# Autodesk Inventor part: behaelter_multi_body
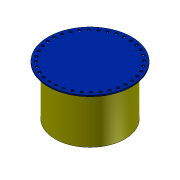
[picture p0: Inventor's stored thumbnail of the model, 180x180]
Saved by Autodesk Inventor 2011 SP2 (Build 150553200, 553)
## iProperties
Created: 2012-02
Part Number: behaelter_multi_body
Material: S235JRG2
Document SubType Name: Modeling
Designer: SCHALLA
Density: 7.85 g/cm^3
Mass: 508816 g
Surface Area: 67707.6 cm^2
Volume: 64817.3 cm^3
Author: SCHALLA
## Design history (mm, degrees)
sketch "SK_ROHR"
  geometry: C1 r 500 at (0, 0); C2 r 480 at (0, 0); 1 further point
  constraints: 2 centre point, 1 coincident
  dimensions: "d27" = 1000 diameter of C1 (= Rohr_D); "d28" = 20 radial gap between concentric circles of C1 C2 (= Rohr_T)
extrude "E_ROHR" new body sketch "SK_ROHR" stored distance "d29" = 700 (= Rohr_L); taper "d30" = 0 deg
sketch "SK_FLANSCH"
  geometry: L1 (0, 0)-(600, 0); L2 (0, 0)-(41.854, 598.538); L3 (0, 0)-(0, 550); A1 r 600 centre (0, 0) between (600, 0) and (41.854, 598.538); A2 r 550 centre (0, 0) between (38.366, 548.66) and (0, 550); 1 further point
  constraints: 6 end point, 4 point on circle, 2 centre point, 1 coincident, 1 horizontal, 1 perpendicular, 1 point on line
  dimensions: "d31" = 1200 diameter of A1 (= Flansch_D); "d35" = 1100 diameter of A2 (= Flansch_LK); "d46" = 4 deg angle of L2 L3 (= Flansch_Bohrung_Start_Winkel)
extrude "E_FLANSCH" new body sketch "SK_FLANSCH" distance "d33" = 20 (= Flansch_T); taper "d34" = 0 deg
hole "BOHRUNG_FLANSCH" sketch "SK_FLANSCH" diameter "d36" = 40 (= Flansch_Bohrung_D); stored, may be unused: countersink angle "d40" = 90 deg, drill point angle "d42" = 0 deg; dims "d37" = 6, "d38" = 4, "d39" = 2, "d41" = 20 (= Flansch_T)
node "ROHR"
pattern_circular "PATTERN_BOHRUNG_FLANSCH" dims angle "d44" = 360 deg
node "FLANSCH"
other parameters: "Rohr_D" = 1000 [user parameter; used in 2 equation terms], "Rohr_L" = 700 [user parameter; used in 1 equation term], "Rohr_T" = 20 [user parameter; used in 1 equation term], "Flansch_D" = 1200 (computed from Rohr_D) [user parameter; used in 2 equation terms], "Flansch_T" = 20 [user parameter; used in 2 equation terms], "Flansch_LK" = 1100 (computed from Flansch_D) [user parameter; used in 1 equation term], "Flansch_Bohrung_Start_Winkel" = 4 deg [user parameter; used in 1 equation term], "Flansch_Bohrung_D" = 40 [user parameter; used in 1 equation term]
